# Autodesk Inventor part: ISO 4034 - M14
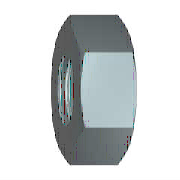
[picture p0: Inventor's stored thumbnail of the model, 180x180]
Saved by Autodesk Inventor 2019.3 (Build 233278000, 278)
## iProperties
Created: 2018-01
Part Number: ISO 4034 - M14
Material: Ocel
Description: Šestihranné matice. Výrobní řada C
Document SubType Name: Modeling
Standard: ISO 4034
Designer: B-hon
Standards Organization: CSN
Language: cs-CZ
Size Designation: M14
Categories: <MemberInstance><Categories><Category DisplayName="Spojovací materiál" InternalName="e4da775c-781d-43d5-af7c-5136215cf5a6" Mnemonic="FSTN"><Category DisplayName
Density: 7.85 g/cm^3
Appearance: Plech
IsCustomPart: 0
Author: B-hon
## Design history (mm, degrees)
sketch "Náčrt1"
  geometry: L1 (-12.124, 0)-(-6.062, 10.5); L2 (-6.062, 10.5)-(6.062, 10.5); L3 (6.062, 10.5)-(12.124, 0); L4 (12.124, 0)-(6.062, -10.5); L5 (6.062, -10.5)-(-6.062, -10.5); L6 (-6.062, -10.5)-(-12.124, 0); 2 further points
  constraints: 12 end point, 1 coincident, 1 horizontal, 11 other
  dimensions: "d0" = 24.24871 distance of L3.end L1.start (= 1.1547 x SW)
extrude "Těleso" new body sketch "Náčrt1" distance "d1" = 13.9 (= KOH); taper "d2" = 0 deg
sketch "Náčrt2"
  geometry: L1 (0, 6.062)-(0, 12.124) reference; L2 (0, 12.124)-(13.9, 12.124) reference; L3 (13.9, 6.062)-(13.9, 12.124) reference; L4 (-2.78, 0)-(16.68, 0) reference; L5 (0.938, 12.124)-(0, 10.5); L6 (12.962, 12.124)-(13.9, 10.5)
  constraints: 4 end point, 4 point on line
  dimensions: "d3" = 30 deg angle of L1 L5 (= ANG1); "d4" = 30 deg angle of L3 L6 (= ANG2); "d5" = 21 diameter of L5.end L4 (= SW0); "d6" = 21 diameter of L6.end L4 (= SW01)
revolve "Zkosení1" sketch "Náčrt2" stored, may be unused: angle "d7" = 90 deg
sketch "Náčrt3"
  geometry: A1 r 10.5 centre (0, 0) between (-5.25, -9.093) and (5.25, -9.093) reference; 1 further point
  constraints: 1 coincident
hole "Závit" sketch "Náčrt3" at (0, 0) diameter "d25" = 11.835; stored, may be unused: countersink angle "d29" = 82 deg, drill point angle "d31" = 118 deg; dims "d26" = 6, "d27" = 4, "d28" = 2, "d30" = 8
workaxis "Work Axis1"
workplane "Work Plane1"
body "Solid1"
chamfer "Zkosení2" distance "d8" = 1.08253 (= -0.5 x GD1 + 0.5 x NND); stored, may be unused: angle "d9" = 30 deg, second distance "d40" = 1.08253 (= -0.5 x GD1 + 0.5 x NND)
chamfer "Zkosení3" distance "d10" = 1.08253 (= -0.5 x GD1 + 0.5 x NND); stored, may be unused: angle "d11" = 30 deg, second distance "d41" = 1.08253 (= -0.5 x GD1 + 0.5 x NND)
other parameters: "ANG1" = 30 deg [user parameter; used in 1 equation term], "ANG2" = 30 deg [user parameter; used in 1 equation term], "NND" = 14 [user parameter; used in 4 equation terms], "KOH" = 13.9 [user parameter; used in 1 equation term], "SW" = 21 [user parameter; used in 4 equation terms], "SW0" = 21 (= SW) [user parameter; used in 1 equation term], "SW01" = 21 (= SW) [user parameter; used in 1 equation term], "GD1" = 11.83494 (computed from THREADDIA, PTC, TOA) [user parameter; used in 4 equation terms], "d13" = 0, "d14" = 0, "d39" = 0, "d42" = 0, "GUL" = 1.08253 (= 0.541266 x PTC) [user parameter], "TPU" = 5 (computed from PTC) [user parameter], "THREADDIA" = 14 [user parameter; used in 1 equation term], "TOA" = 30 deg [user parameter; used in 1 equation term], "PTC" = 2 [user parameter; used in 4 equation terms], "E0" = 24.255 (= 1.155 x SW) [user parameter], "GAL" = 1.08253 (= 0.541266 x PTC) [user parameter]
